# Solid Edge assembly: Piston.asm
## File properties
Title: Piston Assembly
Author: Dan
Template: Normal.asm
Last saved by: Dan
Revision: 55
Application: Solid Edge
Project Name: Piston Pump P52
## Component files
Piston.par
Piston Ball Retaining Clip.psm
Ball Dia11.par
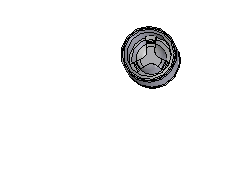
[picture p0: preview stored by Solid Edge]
